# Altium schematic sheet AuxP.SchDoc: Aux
size A3; Date: Not shown in title block; ApprovedBy: Not shown in title block; CheckedBy: Not shown in title block; Author: Not shown in title block; CompanyName: Not shown in title block; DrawnBy: Hely Zhang; Engineer: Not shown in title block; Organization: Not shown in title block; Address1: Not shown in title block; Address2: Not shown in title block; Address3: Not shown in title block; Address4: Not shown in title block; DocumentNumber: 4; Revision: Use project parameter SCH_Rev; SheetNumber: 4; SheetTotal: 6; PageSetup: Record=PageOptions¦CenterHorizontal=True¦CenterVertical=True¦PrintScale=1.00¦XCorrection=1.00¦YCorrection=1.00¦PrintKind=0¦BorderSize=5000000¦LeftOffset=0¦BottomOffset=0¦Orientation=2¦PaperLength=1000¦PaperWidth=1000¦Scale=100¦PaperSource=15¦PrintQuality=600¦MediaType=1¦DitherType=10¦PaperKind=Letter¦PrintScaleMode=1
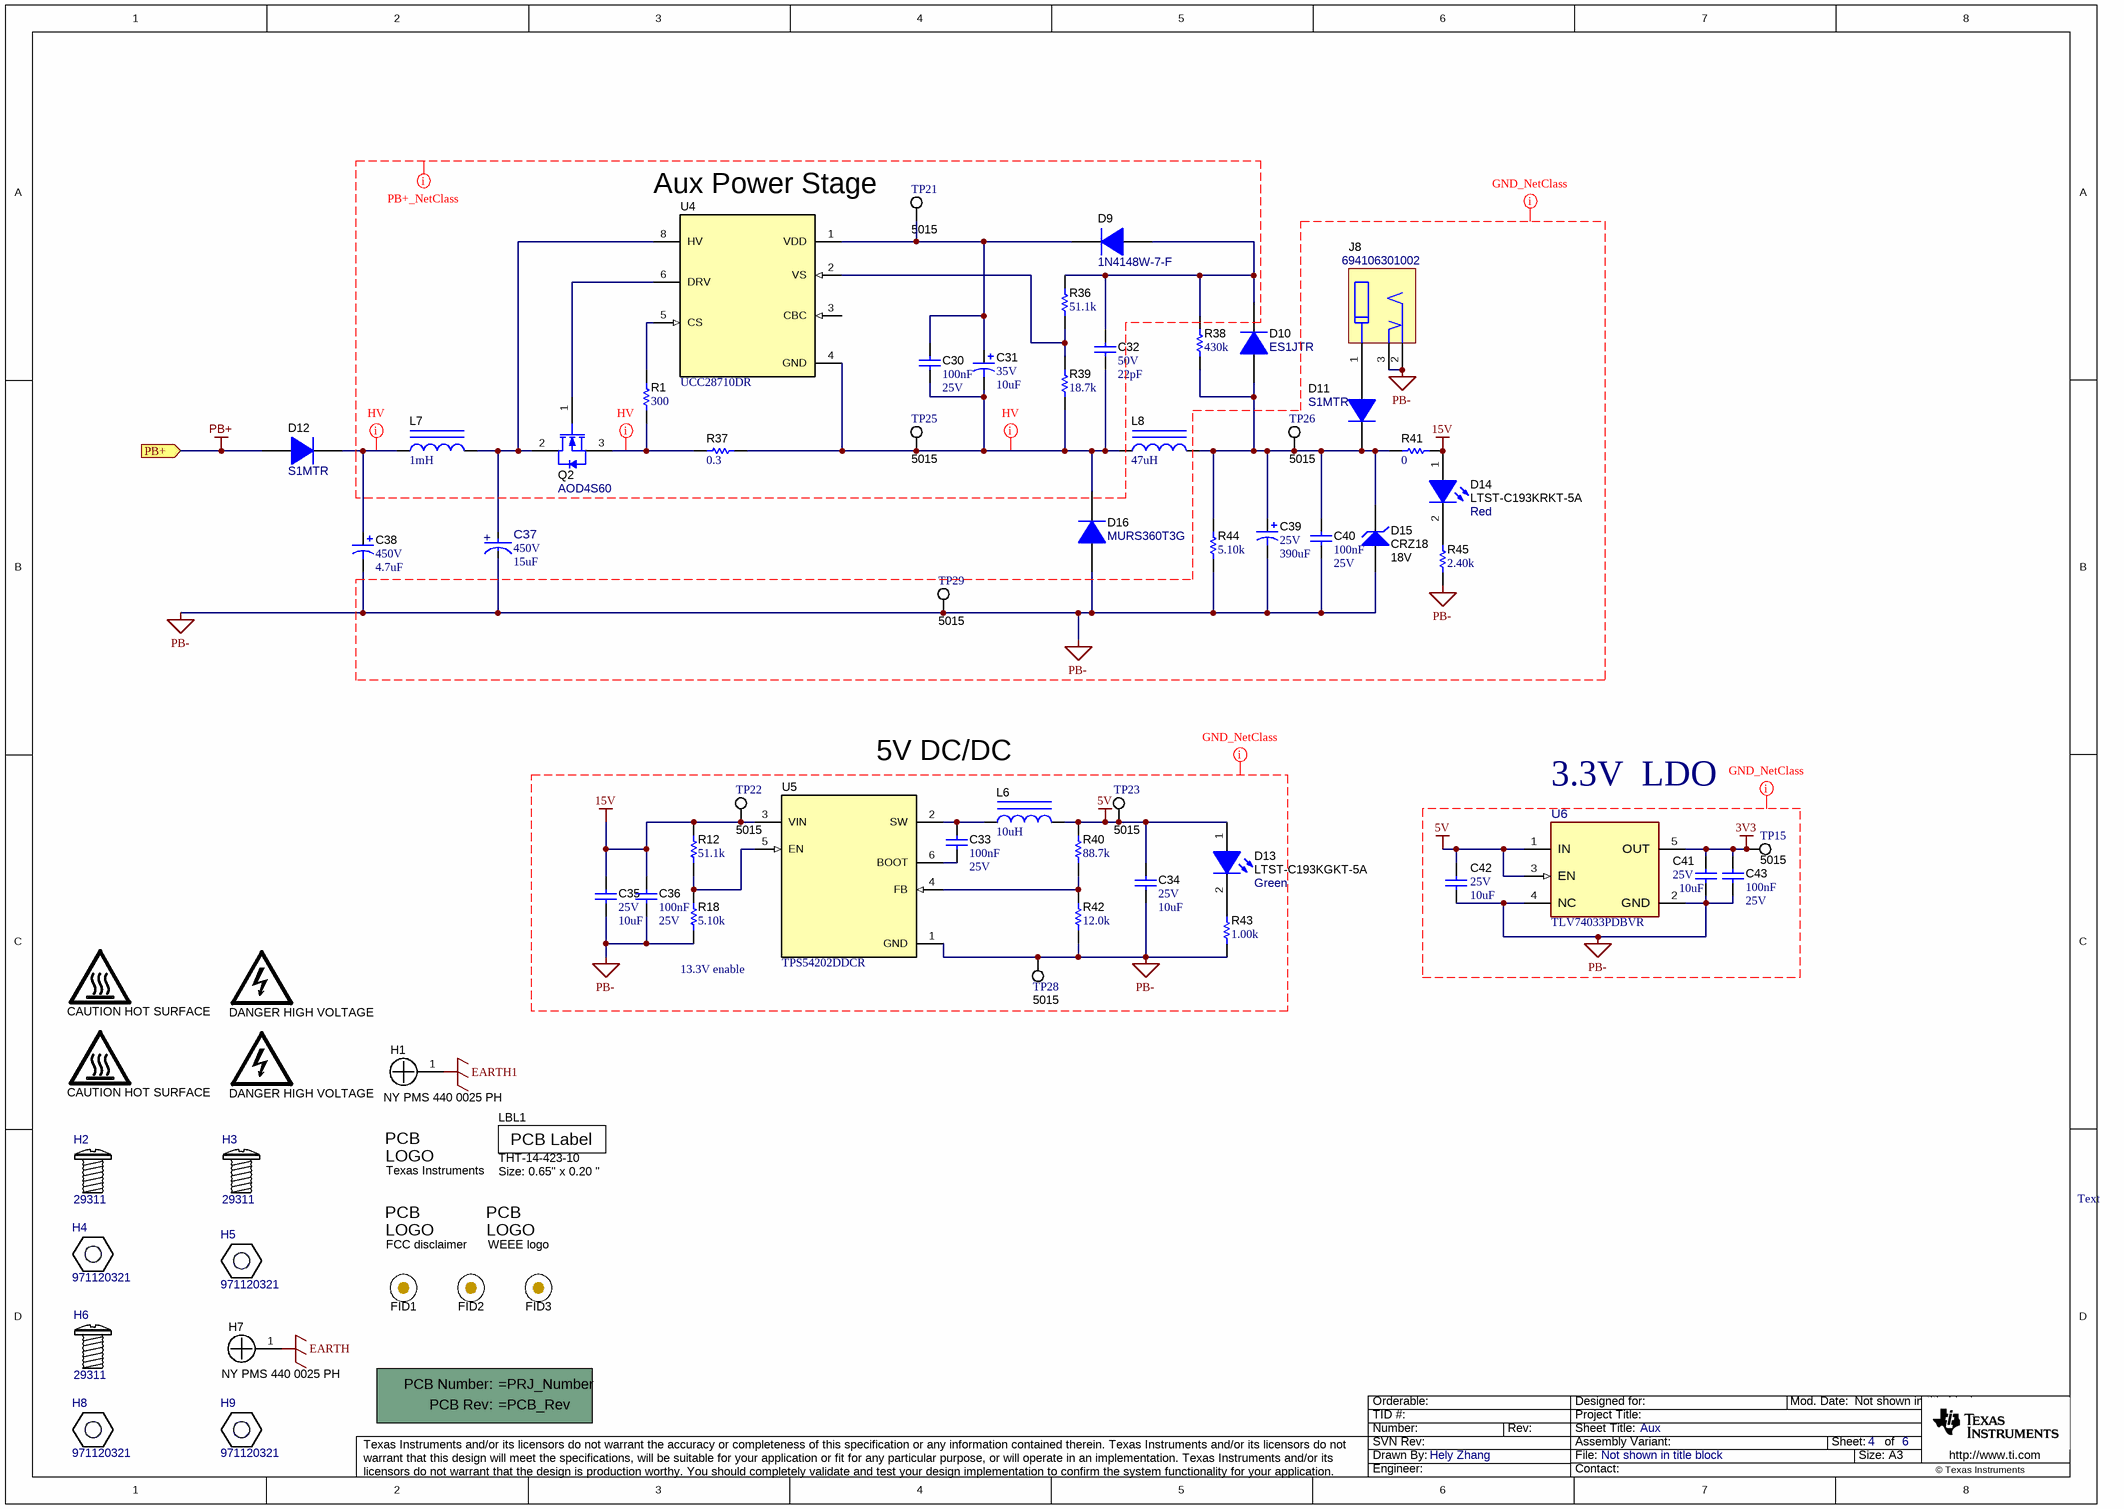
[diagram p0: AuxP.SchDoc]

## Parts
!PCB1  Printed Circuit Board  (value not drawn)  (mechanical)
C30  Cap_F: 100nF  VDC_V: 25V  [0603]  (hidden comment: GRM188R71E104KA01D)
C31  VDC_V: 35V  ValueDisplayed: 10uF  [PW_500x700]  (hidden comment: UPW1V100MDD6)
C32  VDC_V: 50V  ValueDisplayed: 22pF  [0603]  (hidden comment: GRM1885C1H220JA01D)
C33  Cap_F: 100nF  VDC_V: 25V  [0603]  (hidden comment: GRM188R71E104KA01D)
C34  VDC_V: 25V  ValueDisplayed: 10uF  [1206_180]  (hidden comment: GRM31CR71E106KA12L)
C35  VDC_V: 25V  ValueDisplayed: 10uF  [1206_180]  (hidden comment: GRM31CR71E106KA12L)
C36  Cap_F: 100nF  VDC_V: 25V  [0603]  (hidden comment: GRM188R71E104KA01D)
C37  VDC_V: 450V  ValueDisplayed: 15uF  [FP-UCY2W150MPD1TD_RADIAL-MFG]  (hidden comment: UCY2W150MPD1TD)
C38  VDC_V: 450V  ValueDisplayed: 4.7uF  [UVY_1000x1250]  (hidden comment: UVY2W4R7MPD1TD)
C39  VDC_V: 25V  ValueDisplayed: 390uF  [HV_800x1500]  (hidden comment: UHV1E391MPD)
C40  Cap_F: 100nF  VDC_V: 25V  [0603]  (hidden comment: GRM188R71E104KA01D)
C41  VDC_V: 25V  ValueDisplayed: 10uF  [1206_180]  (hidden comment: GRM31CR71E106KA12L)
C42  VDC_V: 25V  ValueDisplayed: 10uF  [1206_180]  (hidden comment: GRM31CR71E106KA12L)
C43  Cap_F: 100nF  VDC_V: 25V  [0603]  (hidden comment: GRM188R71E104KA01D)
D9  1N4148W-7-F  [SOD-123]
D10  ES1JTR  [SMA]
D11  S1MTR  [SMA]
D12  S1MTR  [SMA]
D13  LTST-C193KGKT-5A  value Green  [LTST-C193_Green]
D14  LTST-C193KRKT-5A  value Red  [LTST-C193_Red]
D15  CRZ18  value 18V  [SOD-123]
D16  MURS360T3G  [SMC]
FID1  Fiducial  [Fiducial10-20]  (value not drawn)  (no BOM)
FID2  Fiducial  [Fiducial10-20]  (value not drawn)  (no BOM)
FID3  Fiducial  [Fiducial10-20]  (value not drawn)  (no BOM)
H1  NY PMS 440 0025 PH  [NY PMS 440 0025 PH]  (no BOM)
H2  29311  [Keystone29311]
H3  29311  [Keystone29311]
H4  971120321  [Wurth_971120321]
H5  971120321  [Wurth_971120321]
H6  29311  [Keystone29311]
H7  NY PMS 440 0025 PH  [NY PMS 440 0025 PH]  (no BOM)
H8  971120321  [Wurth_971120321]
H9  971120321  [Wurth_971120321]
J8  694106301002  [Wurth_694106301002]
L6  ValueDisplayed: 10uH  [WE_LQS_252012]  (hidden comment: 74404024100)
L7  ValueDisplayed: 1mH  [WE-TI_5075]  (hidden comment: 7447462102)
L8  ValueDisplayed: 47uH  [WE-PD_1280]  (hidden comment: 744770147)
LBL1  THT-14-423-10  Note: Size: 0.65" x 0.20 "  [Label_650x200]  (no BOM)
LOGO1  CAUTION HOT SURFACE  [IEC_HotSurface_Small]  (no BOM)
LOGO2  DANGER HIGH VOLTAGE  [IEC_HighVoltage_Small]  (no BOM)
LOGO3  CAUTION HOT SURFACE  [IEC_HotSurface_Small]  (no BOM)
LOGO4  DANGER HIGH VOLTAGE  [IEC_HighVoltage_Small]  (no BOM)
Logo5  Texas Instruments  [TI_Stacked_Overlay_Small]  (no BOM)
Logo6  FCC disclaimer  [FCC_disclaimer_stacked]  (no BOM)
Logo7  WEEE logo  [WEEE_Minimum]  (no BOM)
Q2  AOD4S60  [DPAK]
R1  ValueDisplayed: 300  [0603]  (hidden comment: RC0603FR-07300RL)
R12  ValueDisplayed: 51.1k  [0603]  (hidden comment: RC0603FR-0751K1L)
R18  ValueDisplayed: 5.10k  [0603]  (hidden comment: RC0603FR-075K1L)
R36  ValueDisplayed: 51.1k  [0603]  (hidden comment: RC0603FR-0751K1L)
R37  ValueDisplayed: 0.3  [1206]  (hidden comment: ERJ8BQFR30V)
R38  ValueDisplayed: 430k  [1206]  (hidden comment: RC1206FR-07430KL)
R39  ValueDisplayed: 18.7k  [0603]  (hidden comment: RC0603FR-0718K7L)
R40  ValueDisplayed: 88.7k  [0603]  (hidden comment: RC0603FR-0788K7L)
R41  ValueDisplayed: 0  [0603]  (hidden comment: RC0603JR-070RL)
R42  ValueDisplayed: 12.0k  [0603]  (hidden comment: RC0603FR-0712KL)
R43  ValueDisplayed: 1.00k  [0603]  (hidden comment: RC0603FR-071KL)
R44  ValueDisplayed: 5.10k  [0603]  (hidden comment: RC0603FR-075K1L)
R45  ValueDisplayed: 2.40k  [0603]  (hidden comment: RC0603FR-072K4L)
TP15  5015  [Testpoint_Keystone_Miniature]
TP21  5015  [Testpoint_Keystone_Miniature]
TP22  5015  [Testpoint_Keystone_Miniature]
TP23  5015  [Testpoint_Keystone_Miniature]
TP25  5015  [Testpoint_Keystone_Miniature]
TP26  5015  [Testpoint_Keystone_Miniature]
TP28  5015  [Testpoint_Keystone_Miniature]
TP29  5015  [Testpoint_Keystone_Miniature]
U4  UCC28710DR  [D0007A_N]
U5  TPS54202DDCR  [DDC0006A_N]
U6  TLV74033PDBVR  [DBV0005A-MFG]

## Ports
PB+ (in)

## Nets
3V3: C41.1 C43.1 TP15.1 U6.5(OUT)
5V: C34.1 C42.1 D13.1(A) L6.2 R40.2 TP23.1 U6.1(IN) U6.3(EN)
15V: C35.1 C36.1 D14.1(A) R12.2 R41.2 TP22.1 U5.3(VIN)
EARTH: H7.1
EARTH1: H1.1
PB+: D12.2(A) ; port PB+
PB-: C34.2 C35.2 C36.2 C37.1(CATHODE) C38.2(-) C39.2(-) C40.2 C41.2 C42.2 C43.2 D15.2(A) D16.2(A) J8.2 J8.3 R18.1 R42.1 R43.1 R44.1 R45.2 TP28.1 TP29.1 U5.1(GND) U6.2(GND) U6.4(NC)
NetC30_1: C30.1 C31.1(+) D9.1(K) TP21.1 U4.1(VDD)
NetC30_2: C30.2 C31.2(-) C32.2 D16.1(K) L8.1 R37.2 R39.1 TP25.1 U4.4(GND)
NetC32_1: C32.1 D9.2(A) D10.1(K) R36.2 R38.2
NetC33_1: C33.1 L6.1 U5.2(SW)
NetC33_2: C33.2 U5.6(BOOT)
NetC37_2: C37.2(ANODE) L7.2 Q2.2(D) U4.8(HV)
NetC38_1: C38.1(+) D12.1(K) L7.1
NetC39_1: C39.1(+) C40.1 D10.2(A) D11.1(K) D15.1(K) L8.2 R38.1 R41.1 R44.2 TP26.1
NetD11_2: D11.2(A) J8.1
NetD13_2: D13.2(K) R43.2
NetD14_2: D14.2(K) R45.1
NetQ2_1: Q2.1(G) U4.6(DRV)
NetQ2_3: Q2.3(S) R1.1 R37.1
NetR1_2: R1.2 U4.5(CS)
NetR12_1: R12.1 R18.2 U5.5(EN)
NetR36_1: R36.1 R39.2 U4.2(VS)
NetR40_1: R40.1 R42.2 U5.4(FB)

Not connected (* = marked no-connect by the designer): U4 3(CBC)

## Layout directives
net class HV: NetC30_2, NetC38_1, NetQ2_3
net class GND_NetClass: 3V3, 5V, 15V, PB-
net class PB+_NetClass: (no net found under the mark)

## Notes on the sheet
- Aux Power Stage
- 5V DC/DC
- 3.3V  LDO
- 13.3V enable
- Text

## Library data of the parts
!PCB1 = CMP-0003618-2: Manufacturer: Any
C30 C33 C36 C40 C43 = CMP-0007404-5: CAP, CERM, 0.1 uF, 25 V, +/- 10%, X7R, 0603; Manufacturer: MuRata; ValueDisplayed: 0.1uF; SizeAreaWB_mm2: 4.68; MFG_Status: TI_Obsolete; SizeZ_mm: 1; SizeY_mm: 0.8; Value: 0.1uF; AEC Category: Q200; Value1: Unknown; SizeX_mm: 1.6; TaMin_C: -55°C; Polarized: N; TaMax_C: 125°C; SizeArea_mm2: 1.28; U/M: EA
C31 = CMP-0010551-1: CAP, AL, 10 uF, 35 V, +/- 20%, 0.95 ohm, TH; Manufacturer: Nichicon; TaMin_C: -55°C; ESR_ohm: 0.95; Polarized: Y; SizeAreaWB_mm2: 49; U/M: EA; Value: 10uF; TaMax_C: 105°C; SizeZ_mm: 8; SizeX_mm: 5; Cap_Case: 5x7; SizeArea_mm2: 25; CompType: Capacitor; Cap_F: 10µF; IRMS_A: 120mA; AEC Category: Q200
C32 = CMP-0007196-4: CAP, CERM, 22 pF, 50 V, +/- 5%, C0G/NP0, 0603; Manufacturer: MuRata; TaMin_C: -55°C; Polarized: N; SizeAreaWB_mm2: 4.68; Value1: Unknown; U/M: EA; Value: 22pF; TaMax_C: 125°C; SizeZ_mm: 1; SizeX_mm: 1.6; SizeY_mm: 0.8; SizeArea_mm2: 1.28; AEC Category: Q200
C34 C35 C41 C42 = CMP-0008965-2: CAP, CERM, 10 uF, 25 V, +/- 10%, X7R, 1206; Manufacturer: MuRata; TaMin_C: -55°C; Polarized: N; SizeAreaWB_mm2: 10.92; Value1: Unknown; U/M: EA; Value: 10uF; TaMax_C: 125°C; SizeZ_mm: 1.8; SizeX_mm: 3.2; SizeY_mm: 1.6; Cap_Case: 2220; SizeArea_mm2: 5.12; Cap_F: 10µF; AEC Category: Q200
C37 = CMP-0093148-1: 15µF 450V Aluminum Electrolytic Capacitors Radial, Can 12000 Hrs @ 105°C; Manufacturer: Nichicon; Tolerance_%: 20%; AEC Qualified: Yes; IRMS_A: 185mA; Life: 12000Hours; Dissipation Factor: 24%; AEC Grade: Grade 2; SizeZ_mm: 26.5mm; Leakage Current: 370uA
C38 = CMP-0010276-2: CAP, AL, 4.7 uF, 450 V, +/- 20%, TH; Manufacturer: Nichicon; TaMin_C: -25°C; Polarized: Y; SizeAreaWB_mm2: 144; Value1: Unknown; U/M: EA; Value: 4.7uF; TaMax_C: 105°C; SizeZ_mm: 14; SizeX_mm: 10; Cap_Case: 10x12.5mm; SizeArea_mm2: 100; CompType: Capacitor; AEC Qualified: N; Cap_F: 4.7µF; IRMS_A: 32mA; AEC Category: Q200
C39 = CMP-0010536-1: CAP, AL, 390 uF, 25 V, +/- 20%, 0.046 ohm, TH; Manufacturer: Nichicon; TaMin_C: -40°C; ESR_ohm: 0.046; Polarized: Y; SizeAreaWB_mm2: 100; U/M: EA; Value: 390uF; TaMax_C: 105°C; SizeZ_mm: 17.5; SizeX_mm: 8; Cap_Case: 8x15; SizeArea_mm2: 64; CompType: Capacitor; Cap_F: 390µF; IRMS_A: 1.33A; AEC Category: Q200
D9 = CMP-0029001-2: Diode, Ultrafast, 100 V, 0.15 A, SOD-123; Manufacturer: Diodes Inc.; SizeX_mm: 3.85; Value2: 1.25V; Green_REACh: Passed; TJmax_C: 150°C; AEC Category: Q101; SizeAreaWB_mm2: 13.095; Value: 100V; Green_Lifecycle: Active; SizeY_mm: 1.7; Value1: 0.15A; SizeArea_mm2: 6.545; Io_A: 150mA; SizeZ_mm: 1.35
D10 = CMP-0067545-2: Diode, Superfast Rectifier, 600 V, 1 A, SMA; Manufacturer: SMC Diode Solutions; SizeZ_mm: 2.87; Io_A: 1A; SizeY_mm: 2.92; SizeAreaWB_mm2: 37.3428; Value: 600V; SizeX_mm: 5.59; SizeArea_mm2: 16.3228; Value2: 1.7V; AEC Qualified: N; TJmax_C: 150°C; AEC Category: Q101; RJC_CperW: 35.0
D11 D12 = CMP-0078438-1: Diode, Standard Recovery Rectifier, 1000 V, 1 A, SMA; Manufacturer: SMC Diode Solutions; SizeAreaWB_mm2: 37.3428; Vr_V: 1kV; SizeArea_mm2: 16.3228; AEC Qualified: N; TJmax_C: 175°C; AEC Category: Q101; Value: 1000V; SizeZ_mm: 2.87; Io_A: 1A; Vf_V: 1.1V; SizeY_mm: 2.92; SizeX_mm: 5.59
D13 = CMP-0079921-3: LED, Green, SMD; Manufacturer: Lite-On; Tjmax_C: 85°C; Value2: 2V; SizeY_mm: 0.8; Io_A: 5mA; SizeAreaWB_mm2: 4.68; Type: AlInGaP; SizeX_mm: 1.6; SizeZ_mm: 0.45; SizeArea_mm2: 1.28; Value1: W
D14 = CMP-0079922-3: LED, Red, SMD; Manufacturer: Lite-On; SizeX_mm: 1.6; Value2: 2V; SizeY_mm: 0.8; Green_REACh: Incomplete; SizeAreaWB_mm2: 4.68; Green_Lifecycle: Not Set; Value1: W; Io_A: 5mA; Type: AlInGaP; SizeZ_mm: 0.45; Tjmax_C: 85°C; SizeArea_mm2: 1.28
D15 = CMP-0005747-4: Diode, Zener, 18 V, 700 mW, SOD-123; Manufacturer: Toshiba; SizeAreaWB_mm2: 13.095; SizeArea_mm2: 6.545; SizeX_mm: 3.85; Value1: 0.7W; SizeY_mm: 1.7; Power_W: 700mW; SizeZ_mm: 1.35; RJA_CperW: 340; AEC Category: Q101
D16 = CMP-0076905-2: Diode, Ultrafast, 600 V, 3 A, SMC; Manufacturer: ON Semiconductor; TJmax_C: 175°C; SizeAreaWB_mm2: 83.2686; Vr_V: 600V; SizeZ_mm: 2.6; SizeArea_mm2: 50.5686; Io_A: 3A; SizeY_mm: 6.22; Value: 600V; SizeX_mm: 8.13; RJC_CperW: 11.0; Value2: 1.25V; Green_REACh: Passed; Green_Lifecycle: Active; AEC Category: Q101
FID1-FID3 = CMP-0077181-1: Fiducial mark.  There is nothing to buy or mount.
H1 H7 = CMP-0003617-1: Machine Screw, Round, #4-40 x 1/4, Nylon, Philips panhead; Manufacturer: B&F Fastener Supply; CompType: Hardware
H2 H3 H6 = CMP-0003639-1: Screw Pan Head M3; Manufacturer: Keystone; CompType: Hardware
H4 H5 H8 H9 = CMP-0079094-1: HEX STANDOFF M3 STEEL 12MM; Manufacturer: Wurth Elektronik
J8 = CMP-0054778-3: WR-DC DC Power Jack, R/A, TH; Manufacturer: Wurth Elektronik; Gender: Male
L6 = CMP-0063792-1: Inductor, Wirewound, Ferrite, 10 uH, 0.47 A, 0.435 ohm, SMD; Manufacturer: Wurth Elektronik; Isat: 0.85A @ 30% inductance drop; Irms: 0.47A @ 40C rise; Green_Lifecycle: Active; SizeAreaWB_mm2: 10.5; DCR_ohm: 0.435; Green_REACh: Passed; Value: 10uH; Imax_A: 470mA; SizeZ_mm: 1.2; SizeX_mm: 2.5; SizeY_mm: 2; Value2: 0.47A; SizeArea_mm2: 5; Ind_H: 10µH; AEC Category: Q200
L7 = CMP-0064739-2: Inductor, Unshielded Drum Core, Ferrite, 1 mH, 0.25 A, 4.38 ohm, TH; Manufacturer: Wurth Elektronik; Isat: 0.27A @ 10% inductance drop; Irms: 0.25A @ 40C rise; Green_Lifecycle: Active; SizeAreaWB_mm2: 64; DCR_ohm: 4.38; Green_REACh: Passed; Value: 1mH; Imax_A: 250mA; SizeZ_mm: 8.5; SizeX_mm: 6; Value2: 0.25A; SizeArea_mm2: 36; AEC Category: Q200
L8 = CMP-0064531-2: Inductor, Shielded Drum Core, Ferrite, 47 uH, 2.7 A, 0.076 ohm, SMD; Manufacturer: Wurth Elektronik; Isat: 3A @ 10% inductance drop; Irms: 2.7A @ 40C rise; Green_Lifecycle: Active; SizeAreaWB_mm2: 196; DCR_ohm: 0.076; Green_REACh: Passed; Value: 47uH; Imax_A: 2.7A; SizeZ_mm: 8; SizeX_mm: 12; SizeArea_mm2: 144; Ind_H: 47µH; AEC Category: Q200
LBL1 = CMP-0003625-1: Thermal Transfer Printable Labels, 0.650" W x 0.200" H - 10,000 per roll; Manufacturer: Brady; CompType: Label
LOGO1 LOGO3 = CMP-0074837-1: IEC 61010-1 Hot Surface Warning; SymbolCreator: a0412235; Lib Reference: IEC_HotSurface
LOGO2 LOGO4 = CMP-0074835-1: IEC 61010-1 High Voltage Warning; SymbolCreator: a0412235; Lib Reference: IEC_HighVoltage
Logo5 = CMP-0074838-1: Texas Instrument Corporate Signature; SymbolCreator: a0412235; Lib Reference: TI_Logo; Library Reference: Logo
Logo6 = CMP-0074847-1: FCC_disclaimer; Library Reference: Logo
Logo7 = CMP-0074769-1
Q2 = CMP-0001138-4: MOSFET, N-CH, 600 V, 4 A, DPAK; Alternate Manufacturer: None; Manufacturer: AOS; VdsMax_V: 600V; Vgs_V: 30V; SizeX_mm: 9.91; Value2: 6 nC; SizeY_mm: 6.54; SizeAreaWB_mm2: 101.7114; SizeZ_mm: 2.29; QgTyp_nC: 6; Value: 600V; AEC Category: Q101; SizeArea_mm2: 64.8114; AEC Qualified: N; ChMode: Enhancement; IdsMax_A: 4A
R1 = CMP-0023013-5: RES, 300, 1%, 0.1 W, 0603; Manufacturer: Yageo; Power_W: 100mW; TempCo: 100 ppm/C; Value_Code: 300R; Value: 300; SizeX_mm: 1.6; SizeY_mm: 0.8; SizeZ_mm: 1; Value2: 0.1W; SizeArea_mm2: 1.28; AEC Qualified: N; VDC_V: 75V; AEC Category: Q200; SizeAreaWB_mm2: 4.68
R12 R36 = CMP-0023166-5: RES, 51.1 k, 1%, 0.1 W, 0603; Manufacturer: Yageo; Power_W: 100mW; TempCo: 100 ppm/C; Value_Code: 51k1; Value: 51.1k; EIA_Code: E96; SizeX_mm: 1.6; SizeY_mm: 0.8; SizeZ_mm: 1; Value2: 0.1W; SizeArea_mm2: 1.28; AEC Qualified: N; VDC_V: 75V; AEC Category: Q200; SizeAreaWB_mm2: 4.68
R18 R44 = CMP-0023198-5: RES, 5.10 k, 1%, 0.1 W, 0603; Manufacturer: Yageo; Power_W: 100mW; TempCo: 100 ppm/C; Value_Code: 5k10; Value: 5.10k; Res_ohm: 5.1k; SizeX_mm: 1.6; SizeY_mm: 0.8; SizeZ_mm: 1; Value2: 0.1W; SizeArea_mm2: 1.28; AEC Qualified: N; VDC_V: 75V; AEC Category: Q200; SizeAreaWB_mm2: 4.68
R37 = CMP-0074670-1: RES, 0.3, 1%, 0.5 W, AEC-Q200 Grade 1, 1206; Manufacturer: Panasonic; Power_W: 500mW; TempCo: 250 ppm/C; Value_Code: R300; U/M: EA; Value: 0.3; EIA_Code: E96; SizeX_mm: 3.2; SizeY_mm: 1.6; SizeZ_mm: 1.35; Value2: 0.5W; SizeArea_mm2: 5.12; AEC Qualified: Y; AEC Grade: 1; AEC Category: Q200
R38 = CMP-0018293-2: RES, 430 k, 1%, 0.25 W, 1206; Manufacturer: Yageo America; Power_W: 250mW; TempCo: 100 ppm/C; U/M: EA; Value: 430k; SizeX_mm: 3.2; SizeY_mm: 1.6; SizeZ_mm: 1.35; Value2: 0.25W; SizeArea_mm2: 5.12; VDC_V: 200V; AEC Category: Q200
R39 = CMP-0022851-5: RES, 18.7 k, 1%, 0.1 W, 0603; Manufacturer: Yageo; Power_W: 100mW; TempCo: 100 ppm/C; Value_Code: 18k7; Value: 18.7k; EIA_Code: E96; SizeX_mm: 1.6; SizeY_mm: 0.8; SizeZ_mm: 1; Value2: 0.1W; SizeArea_mm2: 1.28; AEC Qualified: N; VDC_V: 75V; AEC Category: Q200; SizeAreaWB_mm2: 4.68
R40 = CMP-0023304-5: RES, 88.7 k, 1%, 0.1 W, 0603; Manufacturer: Yageo; Power_W: 100mW; TempCo: 100 ppm/C; Value_Code: 88k7; Value: 88.7k; EIA_Code: E96; SizeX_mm: 1.6; SizeY_mm: 0.8; SizeZ_mm: 1; Value2: 0.1W; SizeArea_mm2: 1.28; AEC Qualified: N; VDC_V: 75V; AEC Category: Q200; SizeAreaWB_mm2: 4.68
R41 = CMP-0025885-5: RES, 0, 5%, 0.1 W, 0603; Manufacturer: Yageo; Power_W: 100mW; TempCo: 200 ppm/C; Value_Code: 0000; Value: 0; EIA_Code: E24; SizeX_mm: 1.6; SizeZ_mm: 1; Value2: 0.1W; SizeArea_mm2: 1.28; AEC Qualified: N; VDC_V: 75V; AEC Category: Q200; SizeY_mm: 0.8; SizeAreaWB_mm2: 4.68
R42 = CMP-0022779-5: RES, 12.0 k, 1%, 0.1 W, 0603; Manufacturer: Yageo; Power_W: 100mW; TempCo: 100 ppm/C; Value_Code: 12k0; Value: 12.0k; Res_ohm: 12k; SizeX_mm: 1.6; SizeY_mm: 0.8; SizeZ_mm: 1; Value2: 0.1W; SizeArea_mm2: 1.28; AEC Qualified: N; VDC_V: 75V; AEC Category: Q200; SizeAreaWB_mm2: 4.68
R43 = CMP-0022895-5: RES, 1.00 k, 1%, 0.1 W, 0603; Manufacturer: Yageo; Power_W: 100mW; TempCo: 100 ppm/C; Value_Code: 1k00; Value: 1.00k; EIA_Code: E96; Res_ohm: 1k; SizeX_mm: 1.6; SizeY_mm: 0.8; SizeZ_mm: 1; Value2: 0.1W; SizeArea_mm2: 1.28; AEC Qualified: N; VDC_V: 75V; AEC Category: Q200; SizeAreaWB_mm2: 4.68
R45 = CMP-0022991-5: RES, 2.40 k, 1%, 0.1 W, 0603; Manufacturer: Yageo; Power_W: 100mW; TempCo: 100 ppm/C; Value_Code: 2k40; Value: 2.40k; Res_ohm: 2.4k; SizeX_mm: 1.6; SizeY_mm: 0.8; SizeZ_mm: 1; Value2: 0.1W; SizeArea_mm2: 1.28; AEC Qualified: N; VDC_V: 75V; AEC Category: Q200; SizeAreaWB_mm2: 4.68
TP15 TP21-TP23 TP25 TP26 TP28 TP29 = CMP-0055152-1: Test Point, Miniature, SMT; Manufacturer: Keystone; CNHeader: FALSE; Green_Lifecycle: Active; Green_REACh: Passed; CT: TRUE
U4 = CMP-0067230-2: Constant-Voltage, Constant-Current PWM Controller with Primary-Side Regulation, D0007A (SOIC-7); Alternate Manufacturer: Texas Instruments; SizeAreaWB_mm2: 55.2; U/M: EA; SizeZ_mm: 1.75; SizeX_mm: 6.0; SizeY_mm: 4.9; SizeArea_mm2: 29.4; CompType: IC; AEC Category: Q200; AEC Qualified: N
U5 = CMP-0073969-3: 4.5V to 28V Input, 2A Output, EMI Friendly Synchronous Step-Down Converter, DDC0006A (SOT-23-THIN-6); Alternate PartNumber: TPS54202DDCT; Manufacturer: Texas Instruments; SizeZ_mm: 0.87; SizeX_mm: 1.65; SizeY_mm: 2.95; SizeArea_mm2: 4.8675; CompType: IC; SizeAreaWB_mm2: 10.4675; AEC Category: Q200; AEC Qualified: N; Rating: Catalog
U6 = CMP-0090171-1: 300-mA low-dropout (LDO) regulator with foldback current limit 5-SOT-23 -40 to 125; Manufacturer: Texas Instruments; SizeZ_mm: 1.45mm; Output Type: Fixed; Nominal Supply Current: 50uA; TJmax_C: +85°C; Max Supply Voltage: 5.5V; Standoff Height: 0mm; AEC Qualified: No; Accuracy Percentage: 1%; Output Voltage: 3.3V; Number Of Outputs: 1; Dropout Voltage: 460mV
